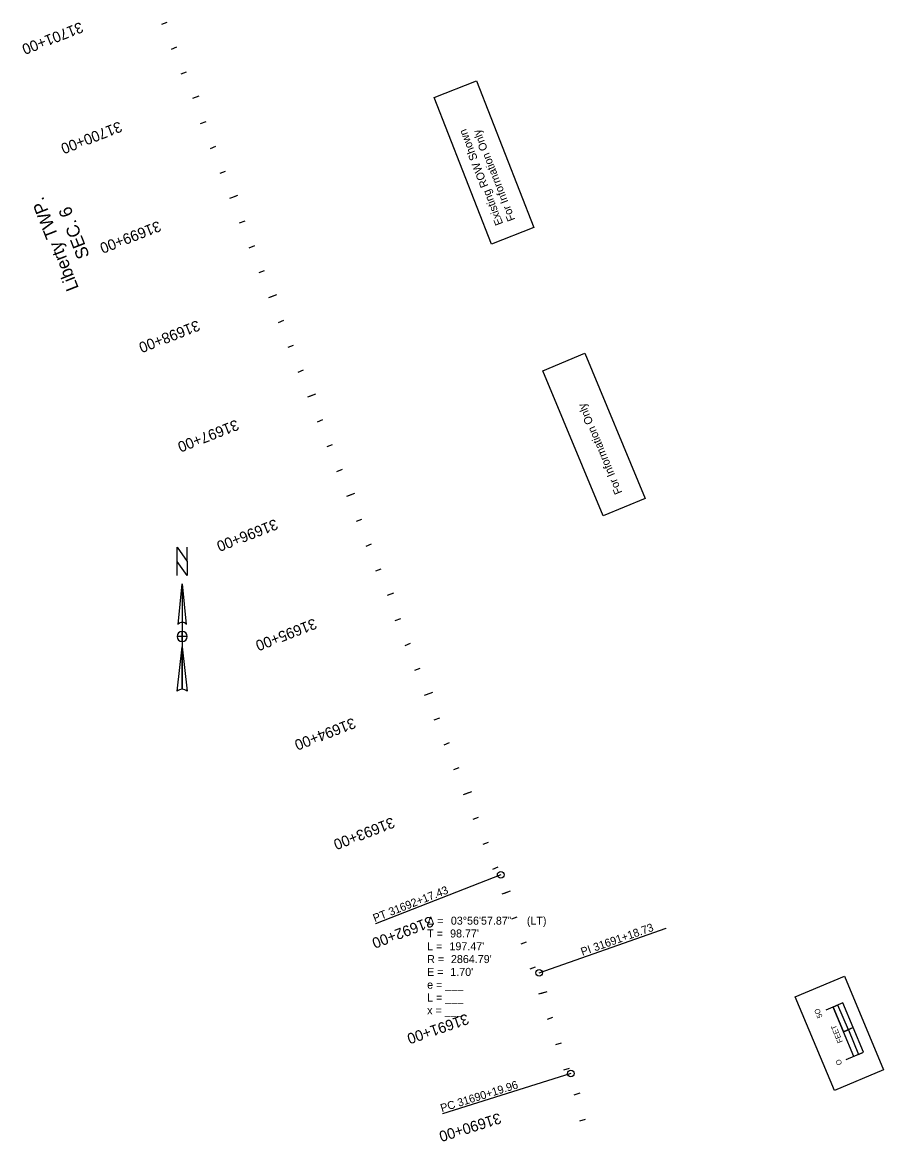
# Model space of a CAD drawing. Extents: x 14087837 to 14090046, y 8544369 to 8548535.
# Drawn here: x 14088244 to 14089051, y 8546405 to 8547454 of the extents above; entities that cross this region are included whole.
import ezdxf

# ---------------------------------------------------------------- set-up
doc = ezdxf.new("R2010")
doc.units = 0
for name, color, linetype in [('_CIVIL_CONSTRUCTION', 7, 'Continuous'), ('Default', 7, 'Continuous'), ('EXT_SNP', 7, 'Continuous'), ('Roadways', 7, 'Continuous'), ('Text', 7, 'Continuous'), ('TextAlignment', 7, 'Continuous'), ('Wetlands', 7, 'Continuous')]:
    doc.layers.add(name, color=color, linetype=linetype)

msp = doc.modelspace()

# ---------------------------------------------------------------- linework, layer by layer
at = {"layer": '_CIVIL_CONSTRUCTION'}
for p, q in [((14088692.2, 8546655.1), (14088574.9, 8546609.2)), ((14088574.9, 8546609.2), (14088574.9, 8546609.2)), ((14088728.2, 8546563.2), (14088847.1, 8546605)), ((14088847.1, 8546605), (14088847.1, 8546605)), ((14088757.8, 8546468.9), (14088637.6, 8546431.2)), ((14088637.6, 8546431.2), (14088637.6, 8546431.2))]:
    msp.add_line(p, q, dxfattribs=at)
for centre in [(14088692.2, 8546655.1), (14088728.2, 8546563.2), (14088757.8, 8546468.9)]:
    msp.add_circle(centre, 3.12, dxfattribs=at)
at = {"layer": 'EXT_SNP'}
for p, q in [((14088394, 8546927.8), (14088397.8, 8546889.7)), ((14088394, 8546927.8), (14088394, 8546828.9)), ((14088390.2, 8546889.7), (14088390.2, 8546889.7)), ((14088390.3, 8546890.1), (14088391, 8546890.9)), ((14088394, 8546873.6), (14088394, 8546873.6)), ((14088389.2, 8546827), (14088394, 8546868.8))]:
    msp.add_line(p, q, dxfattribs=at)
for points in [[(14088683.5, 8547246), (14088629.8, 8547383.3), (14088669.5, 8547398.8), (14088723.3, 8547261.6)], [(14088788.2, 8546991.3), (14088731.5, 8547127.3), (14088770.9, 8547143.8), (14088827.6, 8547007.7)], [(14088398.7, 8546935.4), (14088389.2, 8546948.7), (14088389.2, 8546962), (14088398.7, 8546948.7)]]:
    msp.add_lwpolyline(points, close=True, dxfattribs=at)
for points in [[(14088389.2, 8546935.4), (14088389.2, 8546962), (14088398.7, 8546948.7), (14088398.7, 8546962)], [(14088390.2, 8546889.7), (14088394, 8546927.8), (14088394, 8546891.6)], [(14088398.7, 8546878.3), (14088394, 8546878.3), (14088394, 8546883.1)], [(14088394, 8546873.6), (14088394, 8546878.3), (14088389.2, 8546878.3)], [(14088394, 8546828.9), (14088394, 8546868.8), (14088398.7, 8546827)]]:
    msp.add_lwpolyline(points, dxfattribs=at)
for centre, radius, start, end in [((14088394, 8546886.9), 4.75, 90.0204, 143.1257), ((14088394, 8546886.9), 4.75, 36.8481, 90.0218), ((14088394, 8546878.3), 4.75, 90, 180), ((14088394, 8546878.3), 4.75, 0, 90), ((14088394, 8546878.3), 4.75, 180, 270), ((14088394, 8546878.3), 4.75, 270, 360), ((14088394, 8546822), 6.89, 89.9894, 133.619), ((14088394, 8546822), 6.89, 46.4021, 90.0006)]:
    msp.add_arc(centre, radius, start, end, dxfattribs=at)
at = {"layer": 'Roadways'}
for p, q in [((14088379.6, 8547453.7), (14088374.5, 8547451.7)), ((14088388.7, 8547430.4), (14088383.6, 8547428.4)), ((14088397.8, 8547407.1), (14088392.7, 8547405.1)), ((14088404, 8547382.7), (14088409.7, 8547385)), ((14088416, 8547360.6), (14088410.9, 8547358.6)), ((14088425.1, 8547337.3), (14088420, 8547335.3)), ((14088434.2, 8547314), (14088429.2, 8547312)), ((14088440.5, 8547289.6), (14088446.2, 8547291.8)), ((14088452.5, 8547267.4), (14088447.4, 8547265.5)), ((14088461.6, 8547244.2), (14088456.5, 8547242.2)), ((14088470.7, 8547220.9), (14088465.6, 8547218.9)), ((14088477, 8547196.5), (14088482.7, 8547198.7)), ((14088488.9, 8547174.3), (14088483.8, 8547172.3)), ((14088498, 8547151), (14088493, 8547149.1)), ((14088507.2, 8547127.8), (14088502.1, 8547125.8)), ((14088513.4, 8547103.4), (14088519.1, 8547105.6)), ((14088525.4, 8547081.2), (14088520.3, 8547079.2)), ((14088534.5, 8547057.9), (14088529.4, 8547055.9)), ((14088543.6, 8547034.7), (14088538.5, 8547032.7)), ((14088549.9, 8547010.3), (14088555.6, 8547012.5)), ((14088561.9, 8546988.1), (14088556.8, 8546986.1)), ((14088571, 8546964.8), (14088565.9, 8546962.8)), ((14088580.1, 8546941.5), (14088575, 8546939.5)), ((14088586.3, 8546917.1), (14088592, 8546919.4)), ((14088598.3, 8546895), (14088593.2, 8546893)), ((14088607.4, 8546871.7), (14088602.3, 8546869.7)), ((14088616.5, 8546848.4), (14088611.5, 8546846.4)), ((14088622.8, 8546824), (14088628.5, 8546826.3)), ((14088634.8, 8546801.9), (14088629.7, 8546799.9)), ((14088643.9, 8546778.6), (14088638.8, 8546776.6)), ((14088653, 8546755.3), (14088647.9, 8546753.3)), ((14088659.3, 8546730.9), (14088665, 8546733.1)), ((14088671.2, 8546708.7), (14088666.1, 8546706.8)), ((14088680.3, 8546685.5), (14088675.3, 8546683.5)), ((14088689.5, 8546662.2), (14088684.4, 8546660.2)), ((14088695.7, 8546637.8), (14088701.4, 8546640)), ((14088707.4, 8546615.5), (14088702.3, 8546613.6)), ((14088716.1, 8546592.1), (14088710.9, 8546590.2)), ((14088724.5, 8546568.5), (14088719.4, 8546566.7)), ((14088729.9, 8546543.9), (14088735.7, 8546545.9)), ((14088740.8, 8546521.3), (14088735.7, 8546519.5)), ((14088748.7, 8546497.5), (14088743.5, 8546495.8)), ((14088756.3, 8546473.7), (14088751.1, 8546472.1)), ((14088760.9, 8546449), (14088766.7, 8546450.8)), ((14088771.3, 8546426), (14088766.1, 8546424.4))]:
    msp.add_line(p, q, dxfattribs=at)
at = {"layer": 'Text'}
msp.add_line((14089022.3, 8546511.9), (14089013.1, 8546508.1), dxfattribs=at)
msp.add_line((14089022.3, 8546511.9), (14089013.1, 8546508.1), dxfattribs=at)
for points in [[(14089004.6, 8546453.1), (14088968, 8546540.8), (14089014.2, 8546560), (14089050.7, 8546472.3)], [(14089004.6, 8546453.1), (14088968, 8546540.8), (14089014.2, 8546560), (14089050.7, 8546472.3)], [(14089050.7, 8546472.3), (14089004.6, 8546453.1), (14088968, 8546540.8), (14089014.2, 8546560)], [(14089017.7, 8546510), (14089008, 8546533.1), (14089003.4, 8546531.2), (14089013.1, 8546508.1)], [(14089031.9, 8546488.8), (14089022.3, 8546511.9), (14089017.7, 8546510), (14089027.3, 8546486.9)]]:
    msp.add_lwpolyline(points, close=True, dxfattribs=at)
for points in [[(14089015.8, 8546482.1), (14089031.9, 8546488.8), (14089012.7, 8546535), (14088996.5, 8546528.3)], [(14089022.7, 8546485), (14089003.4, 8546531.2)]]:
    msp.add_lwpolyline(points, dxfattribs=at)
at = {"layer": 'Wetlands'}
for p, q in [((14088404, 8547382.7), (14088409.7, 8547385)), ((14088443.4, 8547290.7), (14088438.3, 8547288.7)), ((14088479.8, 8547197.6), (14088474.7, 8547195.6)), ((14088516.3, 8547104.5), (14088511.2, 8547102.5)), ((14088552.7, 8547011.4), (14088547.7, 8547009.4)), ((14088586.3, 8546917.1), (14088592, 8546919.4)), ((14088625.7, 8546825.1), (14088620.6, 8546823.1)), ((14088662.1, 8546732), (14088657, 8546730)), ((14088698.5, 8546638.9), (14088693.4, 8546636.9)), ((14088732.8, 8546544.9), (14088727.6, 8546543.2)), ((14088760.9, 8546449), (14088766.7, 8546450.8))]:
    msp.add_line(p, q, dxfattribs=at)

# ---------------------------------------------------------------- texts
at = {"layer": '_CIVIL_CONSTRUCTION'}
for s, rotation, p in [('31692+17.43', 21.3828, (14088589, 8546616.5)), ('PT', 21.3828, (14088574.3, 8546610.7)), ('31691+18.73', 19.4081, (14088780.5, 8546583.3)), ('PI ', 19.4081, (14088768.7, 8546579.2)), ('31690+19.96', 17.4334, (14088653, 8546437.7)), ('PC', 17.4334, (14088637.1, 8546432.7))]:
    msp.add_text(s, height=7.5, rotation=rotation, dxfattribs=at).set_placement(p)
for s, p in [('Δ = ', (14088623.3, 8546608.4)), ('03°56\'57.87"', (14088645.5, 8546608.4)), (' (LT)', (14088713.9, 8546608.4)), ('T = ', (14088623.3, 8546596.4)), ("98.77'", (14088644.8, 8546596.4)), ('L = ', (14088623.3, 8546584.4)), ("197.47'", (14088644.2, 8546584.4)), ('R = ', (14088623.3, 8546572.4)), ("2864.79'", (14088645.6, 8546572.4)), ('E = ', (14088623.3, 8546560.4)), ("1.70'", (14088645, 8546560.4)), ('e = ___ ', (14088623.3, 8546548.4)), ('L = ___', (14088623.3, 8546536.4)), ('x = ___', (14088623.3, 8546524.4))]:
    msp.add_text(s, height=7.5, dxfattribs=at).set_placement(p)
at = {"layer": 'Default'}
for s, rotation, p in [('Existing ROW Shown', 111.3828, (14088694.6, 8547265.2)), ('For Information Only', 111.3828, (14088706, 8547269)), ('For Information Only', 112.6265, (14088806.2, 8547013.3))]:
    msp.add_text(s, height=7.5, rotation=rotation, dxfattribs=at).set_placement(p)
at = {"layer": 'Roadways'}
for s, rotation, p in [('31701+00', 201.3828, (14088298.8, 8547454.3)), ('31700+00', 201.3828, (14088335.2, 8547361.2)), ('31699+00', 201.3828, (14088371.7, 8547268)), ('31698+00', 201.3828, (14088408.2, 8547174.9)), ('31697+00', 201.3828, (14088444.6, 8547081.8)), ('31696+00', 201.3828, (14088481.1, 8546988.7)), ('31695+00', 201.3828, (14088517.5, 8546895.6)), ('31694+00', 201.3828, (14088554, 8546802.5)), ('31693+00', 201.3828, (14088590.5, 8546709.3)), ('31692+00', 201.0343, (14088626.7, 8546616.6)), ('31691+00', 199.0343, (14088660.3, 8546525.2)), ('31690+00', 197.4334, (14088690.8, 8546432.2))]:
    msp.add_text(s, height=10.02, rotation=rotation, dxfattribs=at).set_placement(p)
at = {"layer": 'Text'}
for s, p in [('5O', (14088993.7, 8546522)), ('FEET', (14089012.6, 8546498.7)), ('O', (14089012.1, 8546477.9))]:
    msp.add_text(s, height=5, rotation=112.6265, dxfattribs=at).set_placement(p)
at = {"layer": 'TextAlignment'}
for s, p in [('Liberty TWP.', (14088297.3, 8547204.8)), ('SEC. 6', (14088307.5, 8547234.9))]:
    msp.add_text(s, height=12, rotation=111.3828, dxfattribs=at).set_placement(p)
at = {"layer": 'Wetlands'}
for s, rotation, p in [('31700+00', 201.3828, (14088335.2, 8547361.2)), ('31695+00', 201.3828, (14088517.5, 8546895.6)), ('31690+00', 197.4334, (14088690.8, 8546432.2))]:
    msp.add_text(s, height=10.02, rotation=rotation, dxfattribs=at).set_placement(p)

doc.saveas('drawing.dxf')
